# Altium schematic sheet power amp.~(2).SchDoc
size A3
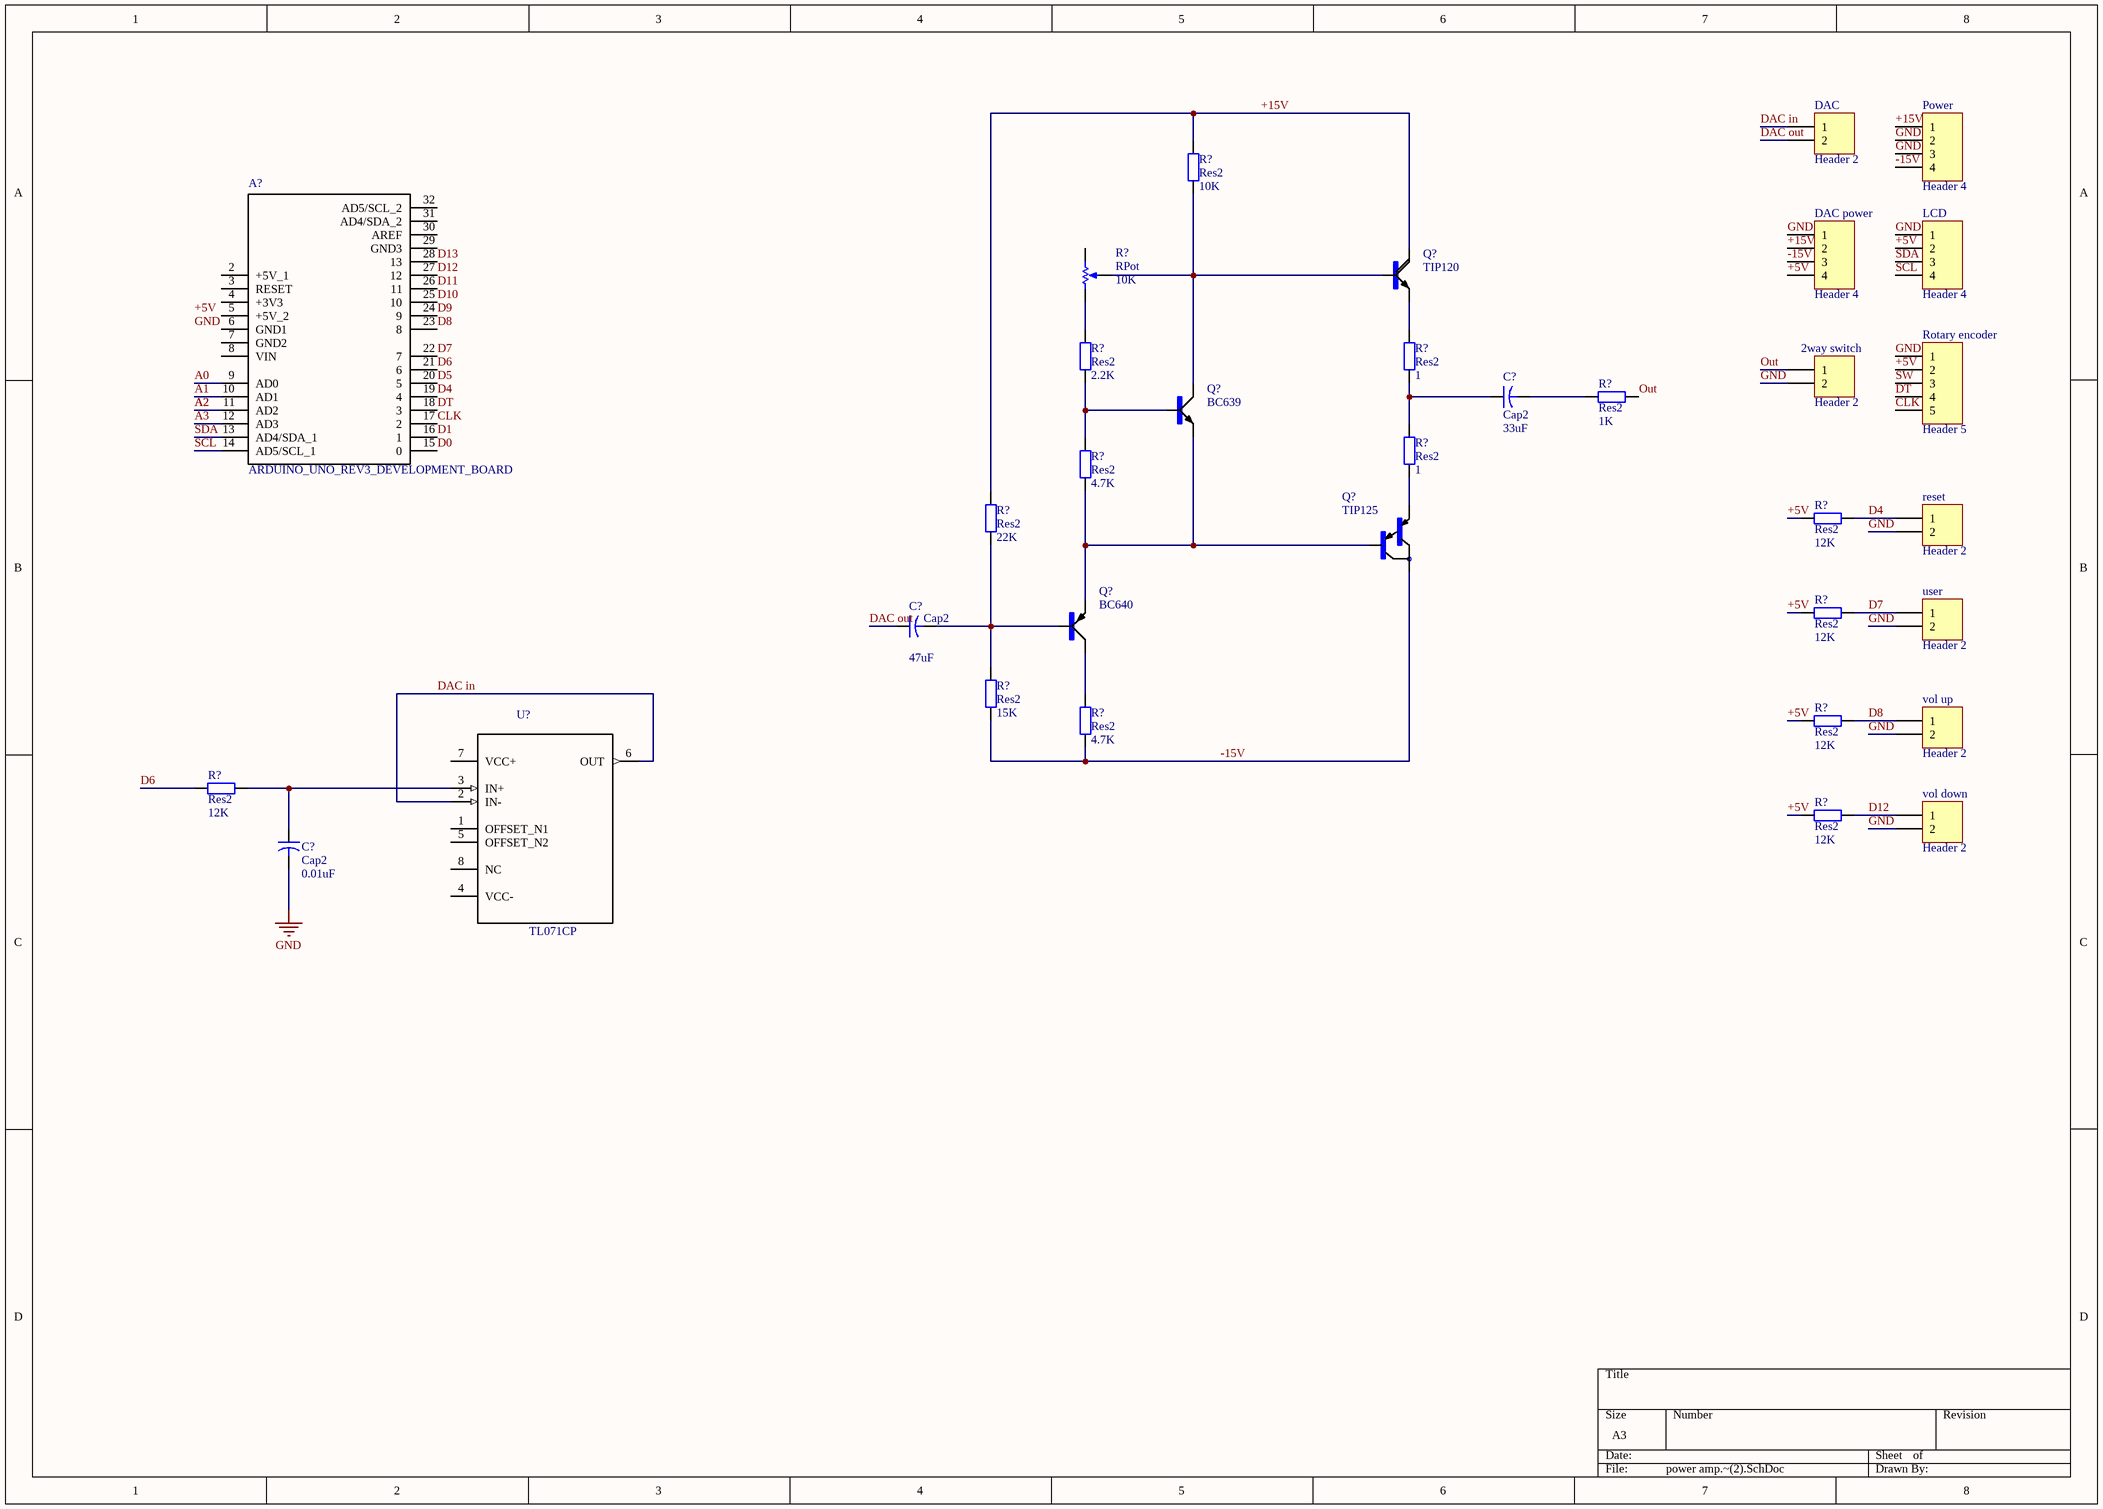
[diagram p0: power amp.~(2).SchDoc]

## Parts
(Parts that share a designator on the sheet are numbered #1, #2 ... from top to bottom, then left to right.)
2way_switch  Header 2  [HDR1X2]
A?  ARDUINO_UNO_REV3_DEVELOPMENT_BOARD  [*ARDUINO_UNO_REV3_DEVELOPMENT_BOARD]
C?#1  Cap2  value 33uF  [CAPR5-4X5]
C?#2  Cap2  value 47uF  [CAPR5-4X5]
C?#3  Cap2  value 0.01uF  [CAPR5-4X5]
DAC  Header 2  [HDR1X2]
DAC_power  Header 4  [HDR1X4]
LCD  Header 4  [HDR1X4]
Power  Header 4  [HDR1X4]
Q?#1  TIP120  [*TO220AH_TIP120(Primary)]
Q?#2  BC639  [*SOT54D_BC639(Primary)]
Q?#3  TIP125  [*TO220]
Q?#4  BC640  [*SOT54D_BC640(Primary)]
R?#1  Res2  value 10K  [AXIAL-0.4]
R?#2  RPot  value 10K  [VR5]
R?#3  Res2  value 2.2K  [AXIAL-0.4]
R?#4  Res2  value 1  [AXIAL-0.4]
R?#5  Res2  value 1K  [AXIAL-0.4]
R?#6  Res2  value 1  [AXIAL-0.4]
R?#7  Res2  value 4.7K  [AXIAL-0.4]
R?#8  Res2  value 12K  [AXIAL-0.4]
R?#9  Res2  value 22K  [AXIAL-0.4]
R?#10  Res2  value 12K  [AXIAL-0.4]
R?#11  Res2  value 15K  [AXIAL-0.4]
R?#12  Res2  value 12K  [AXIAL-0.4]
R?#13  Res2  value 4.7K  [AXIAL-0.4]
R?#14  Res2  value 12K  [AXIAL-0.4]
R?#15  Res2  value 12K  [AXIAL-0.4]
reset  Header 2  [HDR1X2]
Rotary_encoder  Header 5  [HDR1X5]
U?  TL071CP  [*DIP254P762X508-8]
user  Header 2  [HDR1X2]
vol_down  Header 2  [HDR1X2]
vol_up  Header 2  [HDR1X2]

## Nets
GND: 2way_switch.2 C?#3.2 DAC_power.1 LCD.1 Power.2 Power.3 reset.2 Rotary_encoder.1 user.2 vol_down.2 vol_up.2
+5V: DAC_power.4 LCD.2 R?#8.1 R?#10.1 R?#12.1 R?#15.1 Rotary_encoder.2
+15V: DAC_power.2 Power.1 Q?#1.C R?#1.2 R?#9.2
-15V: DAC_power.3 Power.4 Q?#3.2(C) R?#11.1 R?#13.1
A0: A?.9(AD0)
A1: A?.10(AD1)
A2: A?.11(AD2)
A3: A?.12(AD3)
CLK: A?.17(2) Rotary_encoder.5
D0: A?.15(0)
D1: A?.16(1)
D4: A?.19(4) R?#8.2 reset.1
D5: A?.20(5)
D6: A?.21(6) R?#14.1
D7: A?.22(7) R?#10.2 user.1
D8: A?.23(8) R?#12.2 vol_up.1
D9: A?.24(9)
D10: A?.25(10)
D11: A?.26(11)
D12: A?.27(12) R?#15.2 vol_down.1
D13: A?.28(13)
DAC in: DAC.1 U?.2(IN-) U?.6(OUT)
DAC out: C?#2.1 DAC.2
DT: A?.18(3) Rotary_encoder.4
Out: 2way_switch.1 R?#5.1
SCL: A?.14(AD5/SCL_1) LCD.4
SDA: A?.13(AD4/SDA_1) LCD.3
SW: Rotary_encoder.3
NetC?#1_1: C?#1.1 R?#4.1 R?#6.2
NetC?#1_2: C?#1.2 R?#5.2
NetC?#2_2: C?#2.2 Q?#4.B R?#9.1 R?#11.2
NetC?#3_1: C?#3.1 R?#14.2 U?.3(IN+)
NetQ?#1_B: Q?#1.B Q?#2.C R?#1.1 R?#2.3(TAP)
NetQ?#1_E: Q?#1.E R?#4.2
NetQ?#2_B: Q?#2.B R?#3.1 R?#7.2
NetQ?#2_E: Q?#2.E Q?#3.1(B) Q?#4.E R?#7.1
NetQ?#3_3: Q?#3.3(E) R?#6.1
NetQ?#4_C: Q?#4.C R?#13.2
NetR?#2_1: R?#2.1(TOP) R?#3.2

Not connected (* = marked no-connect by the designer): A? 2(+5V_1) 3(RESET) 4(+3V3) 5(+5V_2) 6(GND1) 7(GND2) 8(VIN) 29(GND3) 30(AREF) 31(AD4/SDA_2) 32(AD5/SCL_2); R?#2 2(BOT); U? 1(OFFSET_N1) 4(VCC-) 5(OFFSET_N2) 7(VCC+) 8(NC)

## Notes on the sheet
- Labels drawn without touching a wire or pin: +5V, GND

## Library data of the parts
2way_switch DAC reset user vol_down vol_up = Header 2: Header, 2-Pin
A? = ARDUINO_UNO_REV3_DEVELOPMENT_BOARD: Plated Through Hole Protoboard Arduino Mega Platform Evaluation Expansion Board; MP: ARDUINO UNO REV3 DEVELOPMENT BOARD
C?#1-C?#3 = Cap2: Capacitor
DAC_power LCD Power = Header 4: Header, 4-Pin
Q?#1 = TIP120: Bipolar _BJT_ Transistor NPN - Darlington 60V 5A 2W Through Hole TO-220-3; MF: ON Semiconductor
Q?#2 = BC639: Bipolar _BJT_ Transistor NPN 80V 1A 200MHz 625mW Through Hole TO-92-3; MF: ON Semiconductor
Q?#3 = TIP125: Bipolar _BJT_ Transistor PNP - Darlington 60V 5A 2W Through Hole TO-220-3; MF: ON Semiconductor
Q?#4 = BC640: Bipolar _BJT_ Transistor PNP 80V 500mA 150MHz 625mW Through Hole TO-92-3; MF: ON Semiconductor
R?#1 R?#3-R?#15 = Res2: Resistor
R?#2 = RPot: Potentiometer; Sim Note: Enter the Resistance value and the set point into parameter fields.; Set Position: 0.5
Rotary_encoder = Header 5: Header, 5-Pin
U? = TL071CP: J-FET Amplifier 1 Circuit 8-PDIP; MF: Texas Instruments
